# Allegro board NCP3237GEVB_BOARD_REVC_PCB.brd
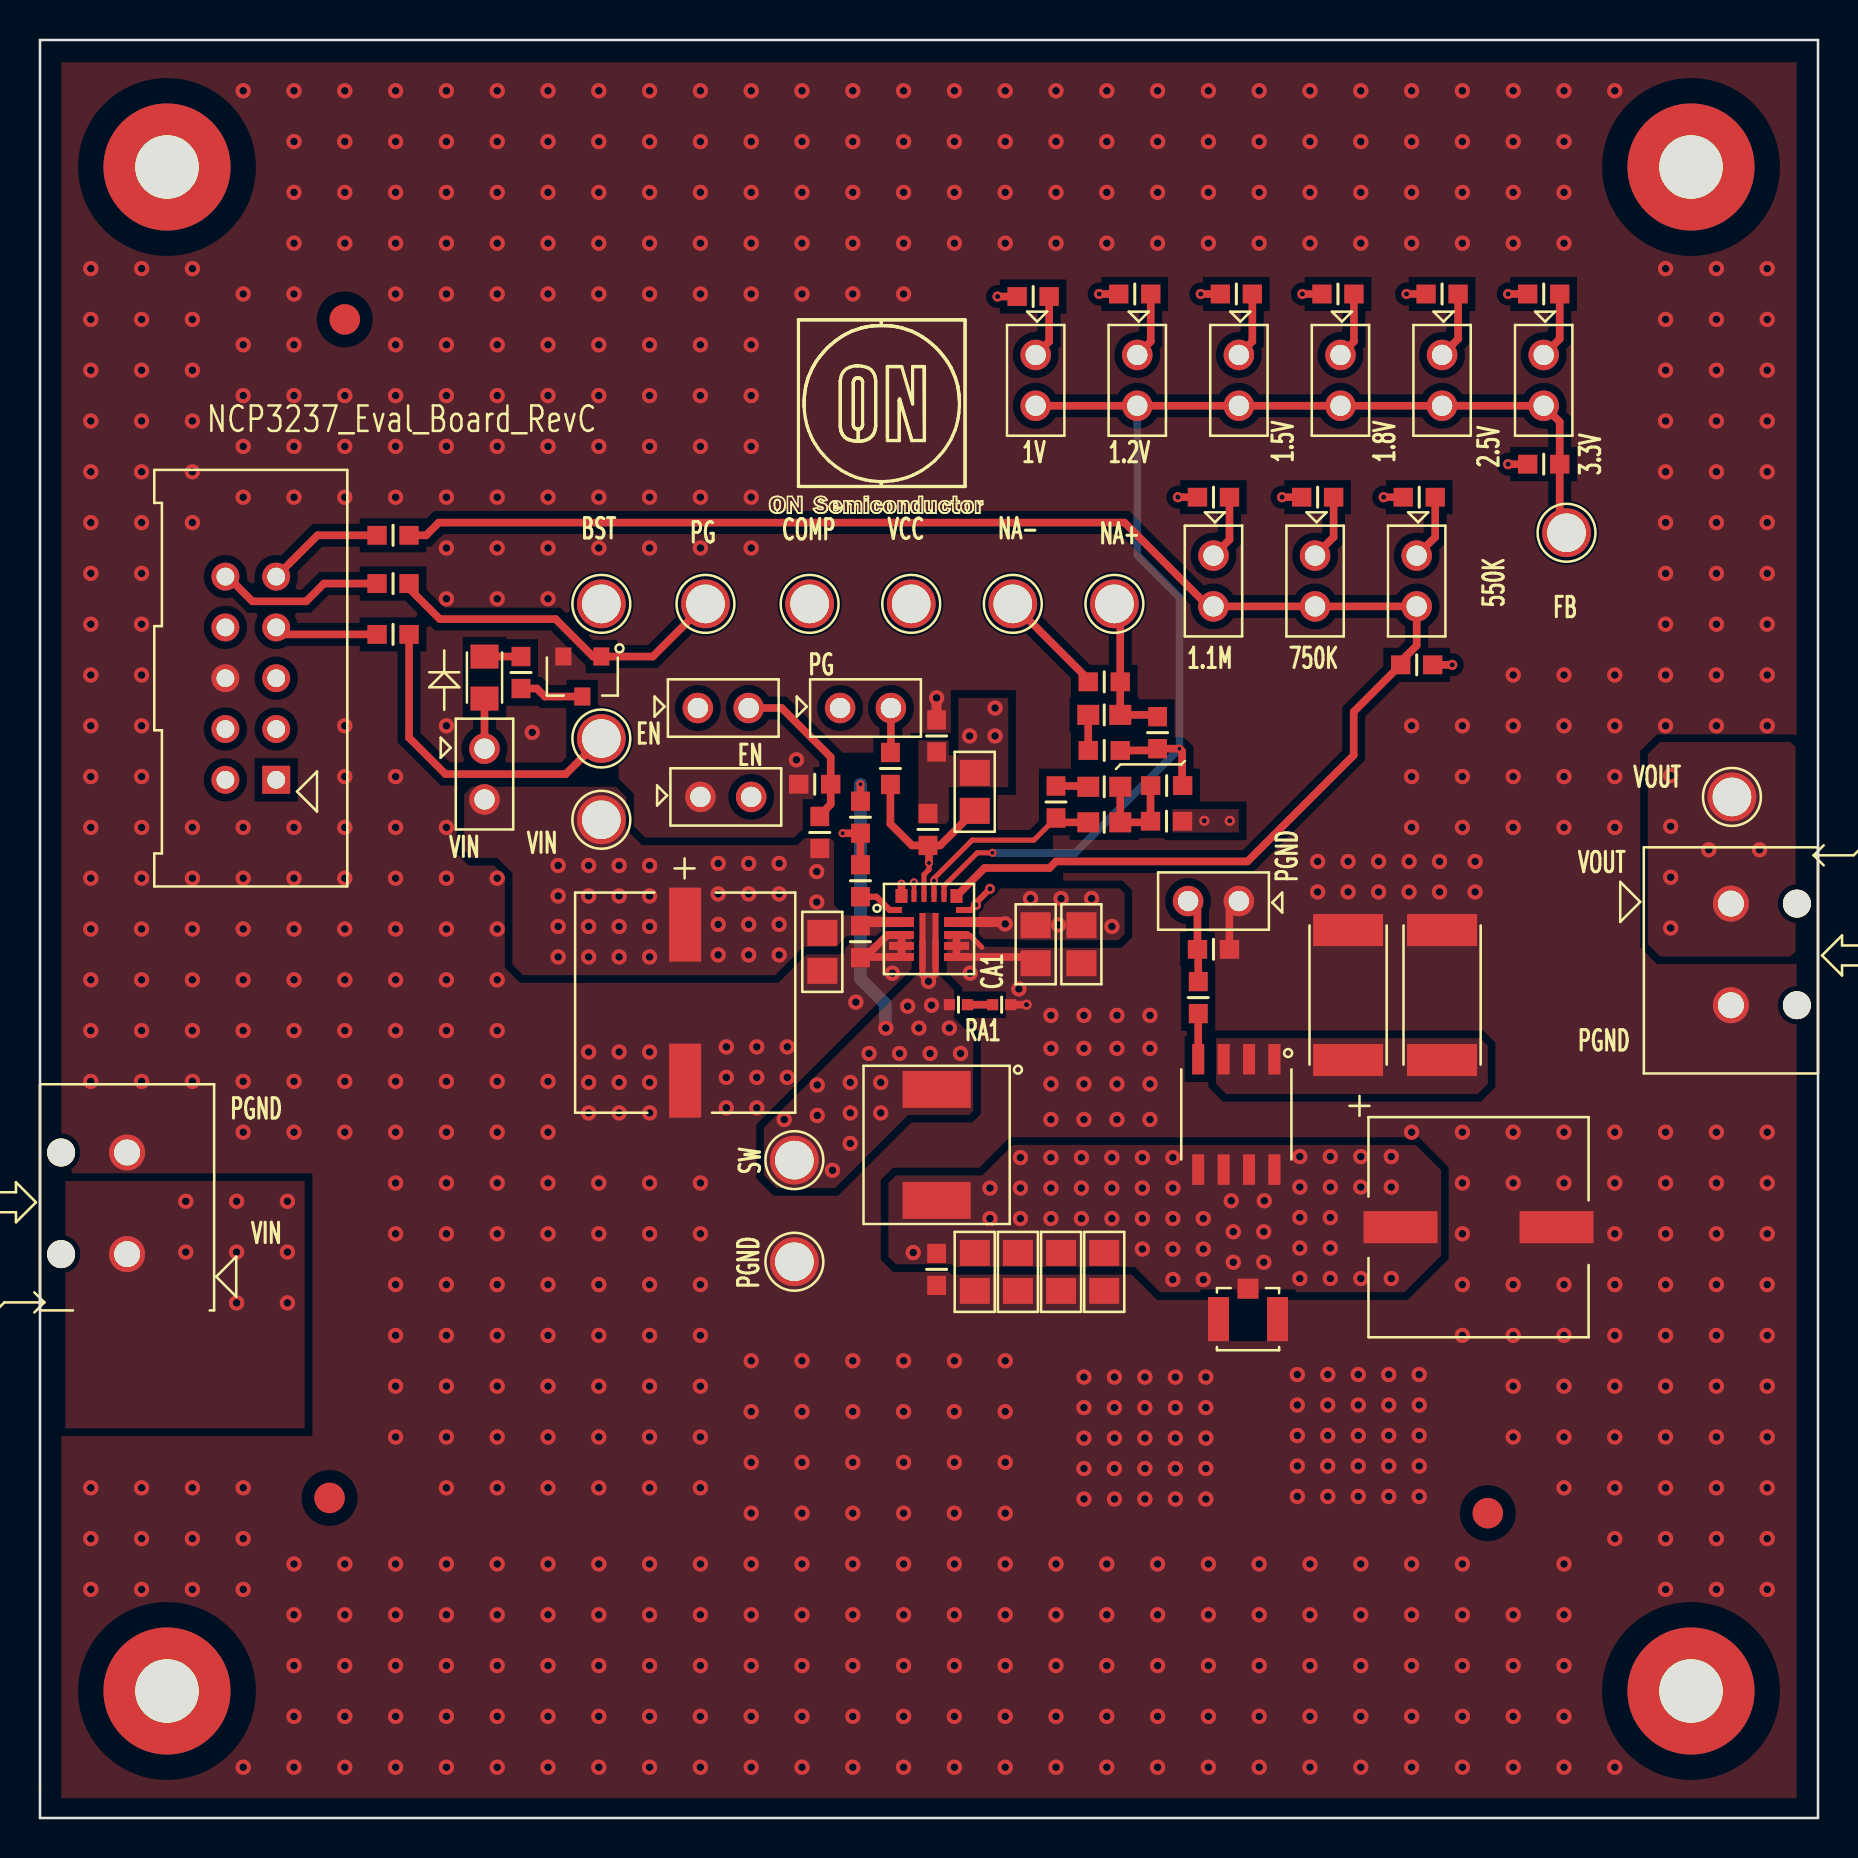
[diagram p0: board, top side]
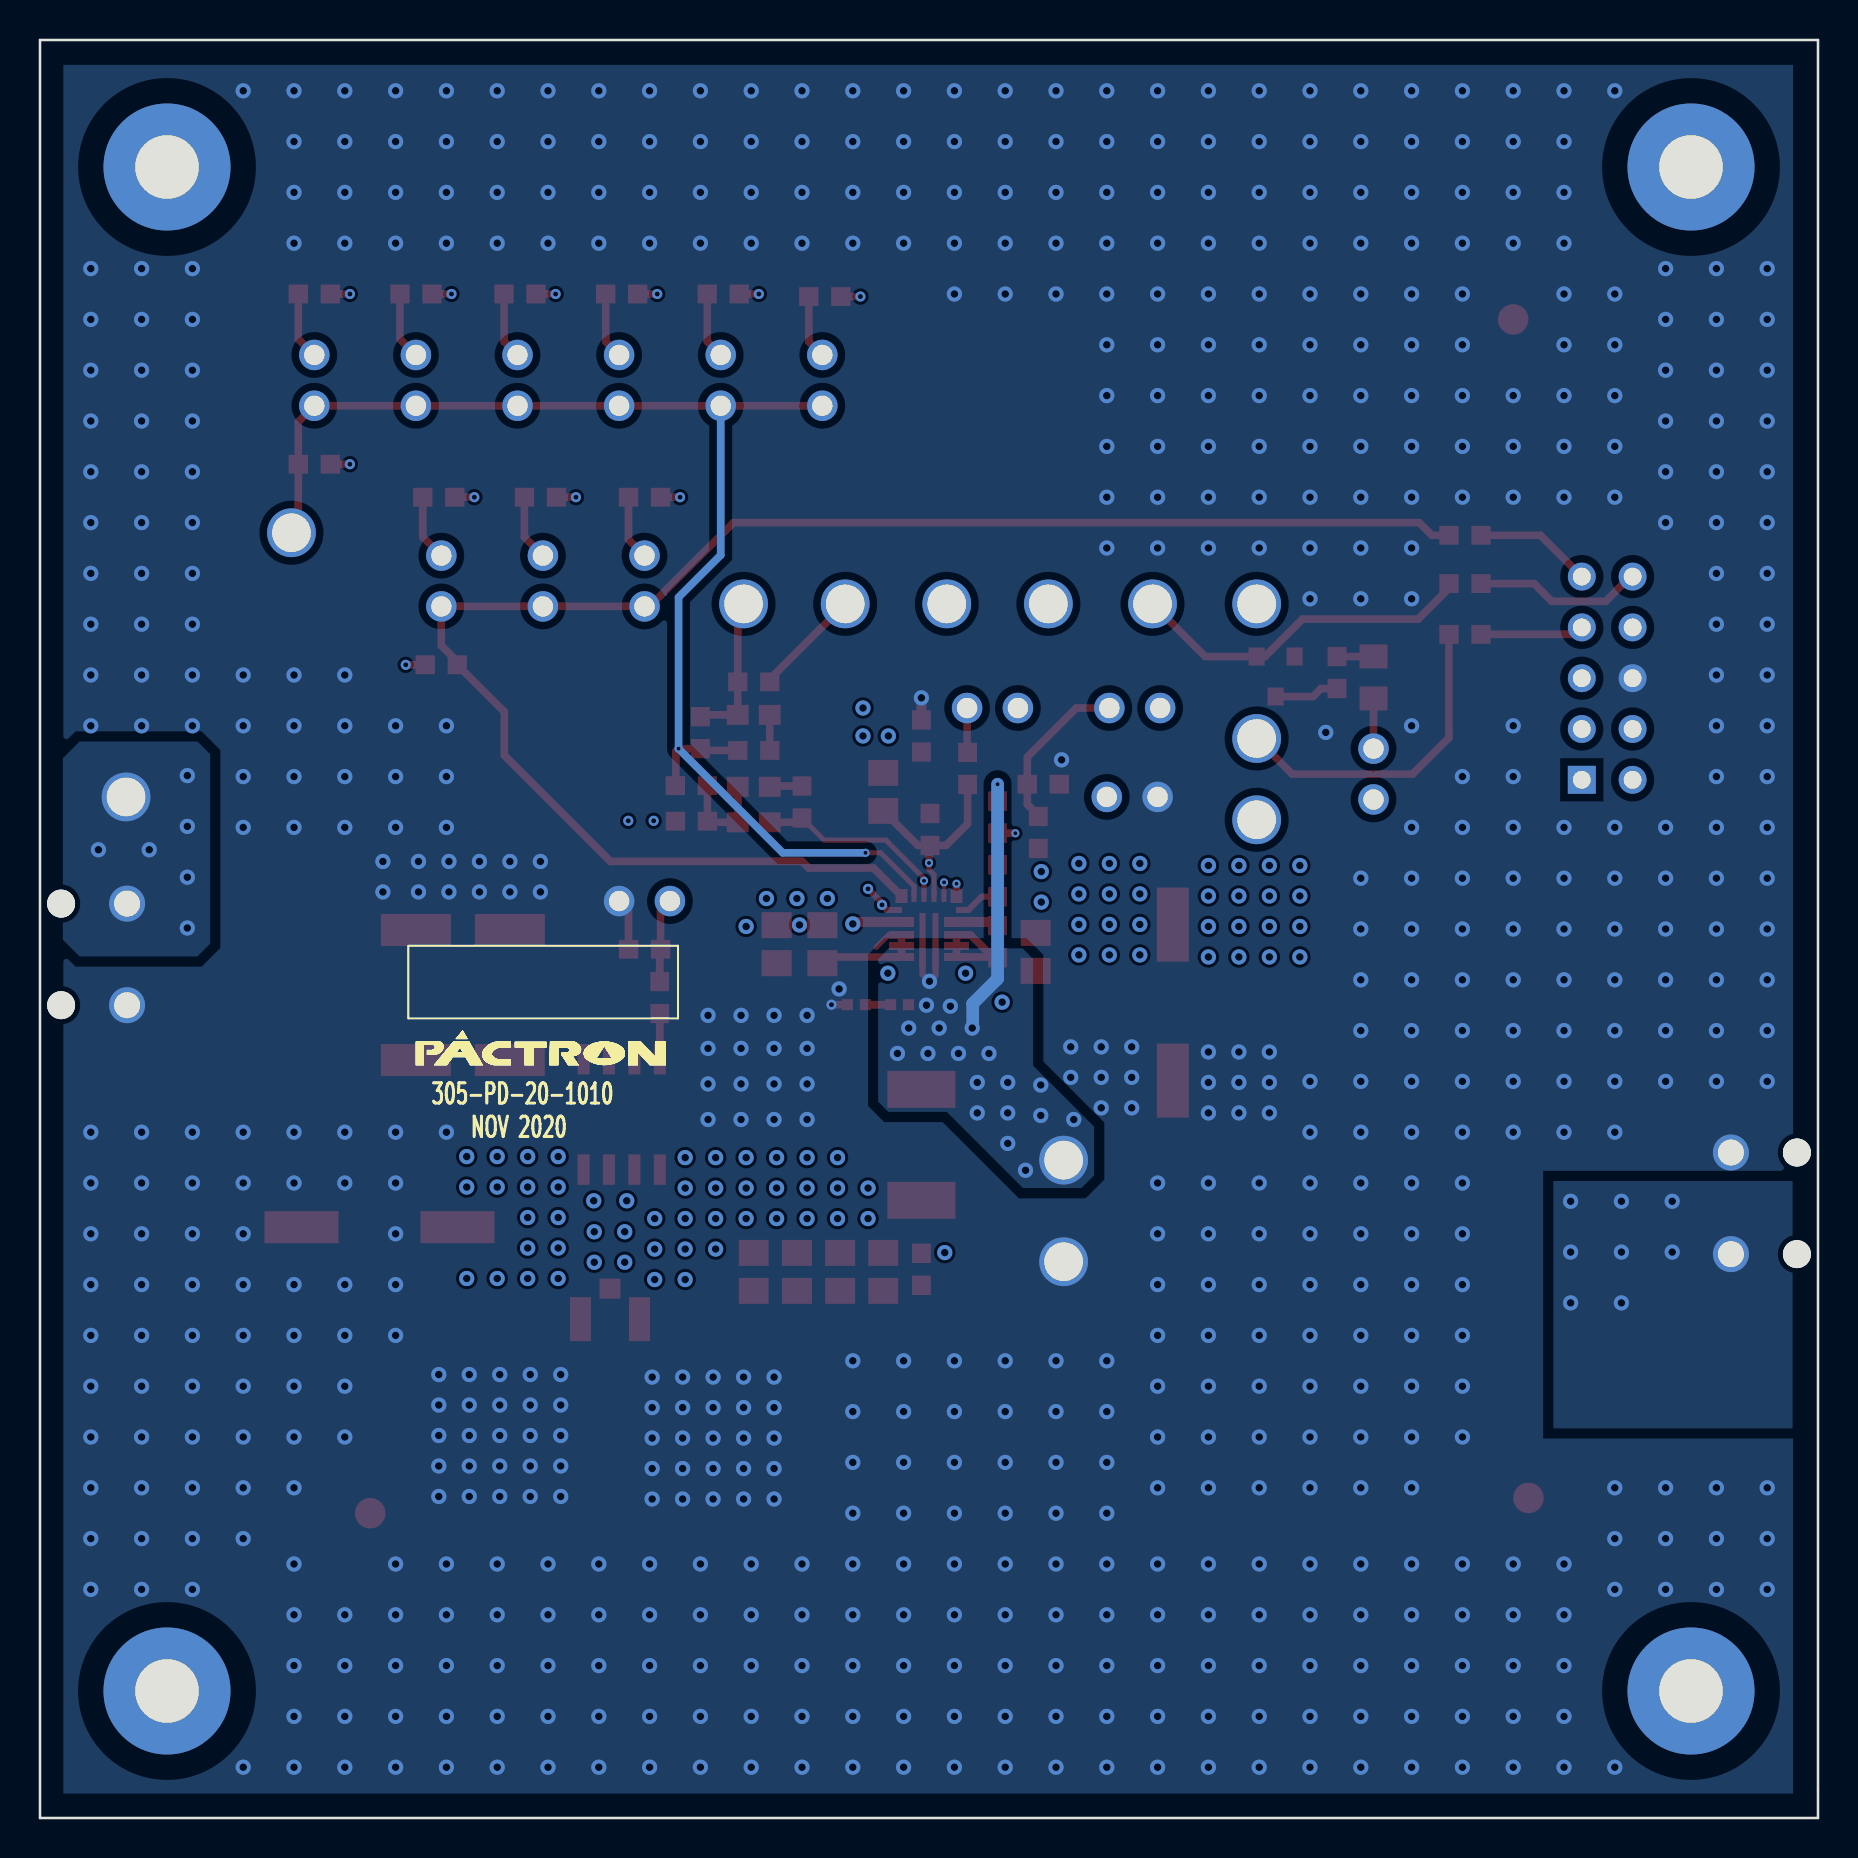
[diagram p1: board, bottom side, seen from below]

Outline 88.9 x 88.9 mm; copper layers: TOP, 02_GND, 03_PWR, BOTTOM. Coordinates in mm from the lower left corner of the outline.
Outline path: 0,88.9 88.9,88.9 88.9,0 0,0 0,88.9

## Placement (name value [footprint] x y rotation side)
C1  22uF  [C0805]  52.07 43.69 270 top
C2  0.1uF  [SMC0603]  41.02 43.81 270 top
C3  0.1uF  [SMC0603]  44.4 49.43 90 top
C4  100uF  [MU_10]  32.26 40.77 270 top
C5  22uF  [C0805]  39.12 43.31 270 top
C6  22uF  [C0805]  49.78 43.69 270 top
C7  0.1uF  [SMC0603]  41.02 50.04 90 top
C8  47uF  [C0805]  46.74 27.3 270 top
C9  47uF  [C0805]  48.9 27.3 270 top
C10  47uF  [C0805]  51.05 27.3 270 top
C11  47uF  [C0805]  53.21 27.3 270 top
C12  0.1uF  [SMC0603]  44.83 27.43 270 top
C13  DNP  [MU_10]  71.93 29.54 0 top
C15  10uF  [C0805]  46.74 51.31 90 top
C17  68pF  [CSMI_0603]  53.21 49.78 180 top
C18  680pF  [CSMI_0603]  53.21 55.16 180 top
C19  1nF  [CSMI_0603]  53.21 51.56 180 top
CA1  DNP  [SMC0402]  48.08 40.67 0 top
D1  GRN  [D0805]  22.23 57.02 270 top
J1  2PIN 1ROW  [JTHI_HDR1R2PS]  58.67 45.85 180 top
J2  2PIN 1ROW  [JTHI_HDR1R2PS]  34.29 51.05 0 top
J3  2PIN 1ROW  [JTHI_HDR1R2PS]  22.23 52.2 270 top
J5  2PIN 1ROW  [JTHI_HDR1R2PS]  49.78 71.88 270 top
J6  2PIN 1ROW  [JTHI_HDR1R2PS]  54.86 71.88 270 top
J7  2PIN 1ROW  [JTHI_HDR1R2PS]  59.94 71.88 270 top
J8  2PIN 1ROW  [JTHI_HDR1R2PS]  58.67 61.85 270 top
J9  2PIN 1ROW  [JTHI_HDR1R2PS]  65.02 71.88 270 top
J10  2PIN 1ROW  [JTHI_HDR1R2PS]  63.75 61.85 270 top
J11  2PIN 1ROW  [JTHI_HDR1R2PS]  70.1 71.88 270 top
J12  2PIN 1ROW  [JTHI_HDR1R2PS]  68.83 61.85 270 top
J13  2PIN 1ROW  [JTHI_HDR1R2PS]  75.18 71.88 270 top
J14  HEADER 5X2_5103308-1  [5103308-1]  10.54 56.99 90 top
J15  2PIN 1ROW  [JTHI_HDR1R2PS]  34.16 55.5 0 top
J16  2PIN 1ROW  [JTHI_HDR1R2PS]  41.27 55.5 0 top
J17  U.FL-R-SMT(10)  [U_FL-R-SMT_10]  60.4 24.94 180 top
L1  1uH  [7_10X6_50X3_00MM]  44.83 33.66 270 top
NOREF  -  []  88.9 88.9 0 top
NOREF#2  -  [unnamed#2]  82.55 6.35 0 top
NOREF#3  -  []  0 0 0 top
NOREF#4  -  [unnamed#2]  82.55 82.55 0 top
NOREF#5  -  []  0 88.9 0 top
NOREF#6  -  [unnamed#2]  15.24 74.93 0 top
NOREF#7  -  []  0 88.9 0 top
NOREF#8  -  [unnamed#2]  6.35 6.35 0 top
NOREF#9  -  [unnamed#2]  72.39 15.24 0 top
NOREF#10  -  []  6.35 82.55 0 top
NOREF#11  -  []  6.35 82.55 0 top
NOREF#12  -  [unnamed#2]  14.48 16 0 top
NOREF#13  -  [unnamed#2]  6.35 82.55 0 top
Q1  NTMS4801  [SO8_PTDSON8_SO8FL_COMBO_8MIL]  59.82 35.18 270 top
Q2  2N7002LT1  [QSMI_SOT23]  27.12 57.07 270 top
R1  DNP  [RSMI_2512]  70.1 41.15 270 top
R2  DNP  [RSMI_2512]  65.41 41.15 270 top
R3  2.0  [SMR0603]  57.91 41.02 90 top
R4  10.0K  [SMR0603]  58.67 43.43 180 top
R5  0.0  [SMR0603]  41.02 46.86 270 top
R6  90.0K  [SMR0603]  38.99 49.28 90 top
R7  30.1K  [SMR0603]  38.73 51.69 180 top
R8  0.0  [SMR0603]  44.83 54.1 270 top
R9  100K  [SMR0603]  42.52 52.48 90 top
R10  10.0  [SMR0603]  53.21 56.81 0 top
R11  150  [SMR0603]  53.21 53.38 0 top
R12  13.7K  [SMR0603]  50.8 50.8 90 top
R13  20K  [SMR0603]  55.88 54.27 270 top
R14  30K  [SMR0603]  49.66 76.07 180 top
R15  20K  [SMR0603]  54.74 76.2 180 top
R16  13.3K  [SMR0603]  59.82 76.2 180 top
R17  511  [SMR0603]  24.05 57.27 270 top
R18  20K  [SMR0603]  58.67 66.04 180 top
R19  10.0K  [SMR0603]  64.9 76.2 180 top
R20  29.4K  [SMR0603]  63.88 66.04 180 top
R21  6.32K  [SMR0603]  70.1 76.2 180 top
R22  40.2K  [SMR0603]  68.96 66.04 180 top
R23  4.42K  [SMR0603]  75.18 76.2 180 top
R24  DNP  [SMR0603]  68.83 57.66 0 top
R25  DNP  [SMR0603]  75.18 67.69 180 top
R26  DNP  [SMR0603]  56.33 49.84 0 top
R27  0  [SMR0603]  56.33 51.62 0 top
R28  0  [SMR0603]  17.65 61.72 0 top
R29  0  [SMR0603]  17.65 64.14 0 top
R30  0  [SMR0603]  17.65 59.18 0 top
RA1  DNP  [SMR0402]  45.92 40.67 0 top
T1  2PIN/TERM BLK  [TERM_BL_2PS]  4.35 30.73 270 top
T2  2PIN/TERM BLK  [TERM_BL_2PS]  84.55 43.18 90 top
TP1  TP  [TPTHI_100R76]  28.07 49.91 0 top
TP2  TP  [TPTHI_100R76]  37.72 32.89 0 top
TP3  TP  [TPTHI_100R76]  28.07 53.98 0 top
TP4  TP  [TPTHI_100R76]  37.72 27.81 0 top
TP5  TP  [TPTHI_100R76]  84.6 51.05 0 top
TP6  TP  [TPTHI_100R76]  38.48 60.71 0 top
TP7  TP  [TPTHI_100R76]  43.56 60.71 0 top
TP8  TP  [TPTHI_100R76]  48.64 60.71 0 top
TP9  TP  [TPTHI_100R76]  53.72 60.71 0 top
TP10  TP  [TPTHI_100R76]  76.33 64.26 0 top
TP11  TP  [TPTHI_100R76]  28.07 60.71 0 top
TP12  TP  [TPTHI_100R76]  33.27 60.71 0 top
U1  NCP3237  [NCP3239]  44.45 44.45 0 top

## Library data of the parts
C1 C3 C5-C12 C15 C17-C19 CA1 = C_2
C2 = C_2: signal model: DEFAULT_CAPACITOR_1pF_1_2
C4 C13 = C_POLARIZED
D1 = LED_0
J1 J3 J5-J13 J15 J16 = J_02PIN_3
J2 = CON2_4
J14 = HEADER 5X2
J17 = BNC
L1 = L
Q1 = Q_NTMS4801NR2G
Q2 = Q_0
R1 R2 = R_0
R3 R5 R8 = R_1
R4 R6 R7 R9 R12-R30 RA1 = R_2
R10 R11 = R
T1 T2 = CON2_3
TP1-TP12 = TP_ROUND
U1 = NCP3239

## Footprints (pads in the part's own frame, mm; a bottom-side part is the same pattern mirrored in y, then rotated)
7_10X6_50X3_00MM
  rect 1.85x3.4 smd: 1(-2.775,0) 2(2.775,0)
5103308-1
  rect 1.397x1.397 hole 0.889: 1(-5.08,-1.27)
  round 1.397 hole 0.889: 2(-5.08,1.27) 3(-2.54,-1.27) 4(-2.54,1.27) 5(0,-1.27) 6(0,1.27) 7(2.54,-1.27) 8(2.54,1.27) 9(5.08,-1.27) 10(5.08,1.27)
C0805
  rect 1.3x1.5 smd: 1(-0.95,0) 2(0.95,0)
CSMI_0603
  rect 1.1x1 smd: 1(-0.8,0) 2(0.8,0)
D0805
  rect 1.2x1.4 smd: 1(1.05,0) 2(-1.05,0)
JTHI_HDR1R2PS
  round 1.524 hole 1.016: 1(-1.27,0) 2(1.27,0)
MU_10
  rect 3.7x1.6 smd: 1(-3.9,0) 2(3.9,0)
NCP3239
  rect 0.6x0.3 smd: 1(-1.65,0.95) 12(1.65,0.95)
  rect 1.25x0.5 smd: 2(-1.375,0.35) 11(1.375,0.35)
  rect 1.25x0.4 smd: 3(-1.375,-0.3) 4(-1.375,-0.85) 5(-1.375,-1.4) 8(1.375,-1.4) 9(1.375,-0.85) 10(1.375,-0.3)
  rect 0.3x2.8 smd: 6(-0.325,-0.6) 7(0.325,-0.6)
  rect 0.6x0.7 smd: 13(1.375,1.65) 18(-1.375,1.65)
  rect 0.25x0.6 smd: 14(0.75,1.65) 15(0.25,1.65) 16(-0.25,1.65) 17(-0.75,1.65)
QSMI_SOT23
  rect 0.9x0.8 smd: 1(-1,0.95) 2(-1,-0.95) 3(1,0)
RSMI_2512
  rect 1.6x3.5 smd: 1(-3.25,0) 2(3.25,0)
SMC0402
  rect 0.559x0.559 smd: 1(-0.45,0) 2(0.45,0)
SMC0603
  rect 0.965x0.94 smd: 1(-0.8,0) 2(0.8,0)
SMR0402
  rect 0.559x0.559 smd: 1(-0.45,0) 2(0.45,0)
SMR0603
  rect 0.965x0.94 smd: 1(-0.8,0) 2(0.8,0)
SO8_PTDSON8_SO8FL_COMBO_8MIL
  rect 1.52x0.6 smd: 1(-2.76,1.905) 2(-2.76,0.635) 3(-2.76,-0.635) 4(-2.76,-1.905) 5(2.76,-1.905) 6(2.76,-0.635) 7(2.76,0.635) 8(2.76,1.905)
TERM_BL_2PS
  round 1.4 hole 1.4 unplated: (-2.54,-3.3) (2.54,-3.3)
  round 1.8 hole 1.3: 1(2.54,0) 2(-2.54,0)
TPTHI_100R76
  round 2.438 hole 1.93: 1(0,0)
U_FL-R-SMT_10
  rect 1.05x1 smd: 1(0,-1.525)
  rect 1.05x2.2 smd: 2(1.475,0) 3(-1.475,0)
unnamed#2
  round 6.35 hole 3.175 unplated: (0,0)

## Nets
GND_SIGNAL_B: C3.2 C15.2 R8.2 R14.2 R15.2 R16.2 R18.2 R19.2 R20.2 R21.2 R22.2 R23.2 R24.2 R25.2 R26.2 U1.12(AGND)
PGND: C1.2 C2.2 C4.2(NEG) C5.2 C6.2 C8.2 C9.2 C10.2 C11.2 C12.2 C13.2(NEG) CA1.2 J1.1 J2.1 J14.6 J17.2(SHIELD1) J17.3(SHIELD2) Q2.2(SOURCE) R1.1 R2.1 R4.1 R7.2 R8.1 T1.2 T2.2 TP4.1 U1.3(PGND1) U1.4(PGND2) U1.5(PGND3) U1.8(PGND4) U1.9(PGND5) U1.10(PGND6)
VIN: C1.1 C2.1 C4.1(POS) C5.1 C6.1 J3.2 R6.1 T1.1 TP1.1 U1.2(VIN1) U1.11(VIN2)
BST: R5.2 U1.1(BST)
COMP: C17.2 R12.1 TP6.1 U1.15(COMP)
EN: J2.2 J15.1 R30.2 TP3.1 U1.17(EN)
FB: J5.2 J6.2 J7.2 J9.2 J11.2 J13.2 R11.2 R13.2 R25.1 R27.2 TP10.1 U1.14(FB)
FSET: J8.2 J10.2 J12.2 R24.1 R29.2 U1.13(FSET)
NA+: C18.1 R10.2 R13.1 TP9.1
PG: J16.1 Q2.1(GATE) R28.2 TP12.1 U1.18(PGOOD)
SW: C7.2 L1.1 RA1.1 TP2.1 U1.6(SW1) U1.7(SW2)
VOUT: C8.1 C9.1 C10.1 C11.1 C12.1 C13.1(POS) J17.1(CENTER) L1.2 Q1.5(DRAIN5) Q1.6(DRAIN6) Q1.7(DRAIN7) Q1.8(DRAIN8) R10.1 T2.1 TP5.1 TP8.1
N16789551: C19.2 R12.2
N16789670: J5.1 R14.1
N16789692: J6.1 R15.1
N16789714: J7.1 R16.1
N16789742: J9.1 R19.1
N16789764: J11.1 R21.1
N16789776: J13.1 R23.1
N16792987: Q1.1(SOURCE1) Q1.2(SOURCE2) Q1.3(SOURCE3) R1.2 R2.2
N16793020: J1.2 R3.2 R4.2
N16793026: Q1.4(GATE) R3.1
N16793275: Q2.3(DRAIN) R17.2
N16793363: C3.1 C15.1 R9.1 TP7.1 U1.16(VCC)
N16793705: J8.1 R18.1
N16793731: J10.1 R20.1
N16793749: J12.1 R22.1
N16797798: C7.1 R5.1 TP11.1
N16798023: CA1.1 RA1.2
N16816279: C17.1 C19.1 R26.1 R27.1
N16820769: D1.2(CATHODE) R17.1
N16820774: D1.1(ANODE) J3.1
N16826315: J14.10 R28.1
N16826318: J14.9 R29.1
N16826340: J14.7 R30.1
N16827137: J15.2 R6.2 R7.1
N16827915: J16.2 R9.2
N167900601: C18.2 R11.1

Pads without a net: J14 1 2 3 4 5 8

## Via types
v1: diameter 0.406, hole 0.203, TOP to BOTTOM, 8 vias
v2: diameter 0.508, hole 0.254, TOP to BOTTOM, 16 vias
v3: diameter 0.762, hole 0.381, TOP to BOTTOM, 809 vias

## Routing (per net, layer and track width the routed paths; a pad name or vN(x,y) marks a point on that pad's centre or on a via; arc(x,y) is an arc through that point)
GND_SIGNAL_B: length 12.7
  TOP w0.305: U1.12 46.54,45.4 v2(46.8,45.66) 46.8,45.76 v2(47.5,46.46)
  TOP w0.381: R16.2 v2(58.04,76.2) ; R20.2 v2(62.1,66.04) ; R22.2 v2(67.18,66.04) ; R14.2 v2(47.88,76.07) ; R18.2 v2(56.9,66.04) ; R15.2 v2(52.96,76.2) ; R24.2 v2(70.61,57.66) ; R19.2 v2(63.12,76.2) ; R25.2 v2(73.41,67.69) ; R21.2 v2(68.33,76.2) ; R23.2 v2(73.41,76.2)
  vias: v2(58.22,49.86) v2(59.49,49.86) v3(46.48,54.1) v3(47.75,55.5) v3(47.75,54.1)
PGND: length 16.9
  TOP w0.254: 47.09,43.54 46.48,44.15 U1.10
  TOP w0.381: J1.1 59.47,45.38 R4.1 ; U1.10 U1.9 U1.8 49.47,43.05 C6.2 ; CA1.2 v2(49.33,40.67) ; C2.2 41.24,43.01 42.37,44.15 U1.3 U1.4 U1.5 41.06,43.05 C2.2
  TOP w0.508: R8.1 v3(44.83,56.01)
  vias: v3(2.54,77.47) v3(2.54,74.93) v3(2.54,72.39) v3(2.54,69.85) v3(2.54,67.31) v3(2.54,64.77) v3(2.54,62.23) v3(2.54,59.69) v3(2.54,57.15) v3(2.54,54.61) v3(2.54,52.07) v3(2.54,49.53) v3(2.54,46.99) v3(2.54,44.45) v3(2.54,41.91) v3(2.54,39.37) v3(2.54,36.83) v3(2.54,16.51) v3(2.54,13.97) v3(2.54,11.43) v3(5.08,77.47) v3(5.08,74.93) v3(5.08,72.39) v3(5.08,69.85) v3(5.08,67.31) v3(5.08,64.77) v3(5.08,62.23) v3(5.08,59.69) v3(5.08,57.15) v3(5.08,54.61) v3(5.08,52.07) v3(5.08,49.53) v3(5.08,46.99) v3(5.08,44.45) v3(5.08,41.91) v3(5.08,39.37) v3(5.08,36.83) v3(5.08,16.51) v3(5.08,13.97) v3(5.08,11.43) v3(7.62,77.47) v3(7.62,74.93) v3(7.62,72.39) v3(7.62,69.85) v3(7.62,67.31) v3(7.62,64.77) v3(7.62,49.53) v3(7.62,46.99) v3(7.62,44.45) v3(7.62,41.91) v3(7.62,39.37) v3(7.62,36.83) v3(7.62,16.51) v3(7.62,13.97) v3(7.62,11.43) v3(10.16,86.36) v3(10.16,76.2) v3(10.16,73.66) v3(10.16,71.12) v3(10.16,68.58) v3(10.16,66.04) v3(10.16,49.53) v3(10.16,46.99) v3(10.16,44.45) v3(10.16,41.91) v3(10.16,39.37) v3(10.16,36.83) v3(10.16,34.29) v3(10.16,16.51) v3(10.16,13.97) v3(10.16,11.43) v3(10.16,2.54) v3(12.7,86.36) v3(12.7,83.82) v3(12.7,81.28) v3(12.7,78.74) v3(12.7,76.2) v3(12.7,73.66) v3(12.7,71.12) v3(12.7,68.58) v3(12.7,66.04) v3(12.7,49.53) v3(12.7,46.99) v3(12.7,44.45) v3(12.7,41.91) v3(12.7,39.37) v3(12.7,36.83) v3(12.7,34.29) v3(12.7,12.7) v3(12.7,10.16) v3(12.7,7.62) v3(12.7,5.08) v3(12.7,2.54) v3(15.24,86.36) v3(15.24,83.82) v3(15.24,81.28) v3(15.24,78.74) v3(15.24,71.12) v3(15.24,68.58) v3(15.24,66.04) v3(15.24,54.61) v3(15.24,52.07) v3(15.24,49.53) v3(15.24,46.99) v3(15.24,44.45) v3(15.24,41.91) v3(15.24,39.37) v3(15.24,36.83) v3(15.24,34.29) v3(15.24,12.7) v3(15.24,10.16) v3(15.24,7.62) v3(15.24,5.08) v3(15.24,2.54) v3(17.78,86.36) v3(17.78,83.82) v3(17.78,81.28) v3(17.78,78.74) v3(17.78,76.2) v3(17.78,73.66) v3(17.78,71.12) v3(17.78,68.58) v3(17.78,66.04) v3(17.78,52.07) v3(17.78,49.53) v3(17.78,46.99) v3(17.78,44.45) v3(17.78,41.91) v3(17.78,39.37) v3(17.78,36.83) v3(17.78,34.29) v3(17.78,31.75) v3(17.78,29.21) v3(17.78,26.67) v3(17.78,24.13) v3(17.78,21.59) v3(17.78,19.05) v3(17.78,12.7) v3(17.78,10.16) v3(17.78,7.62) v3(17.78,5.08) v3(17.78,2.54) v3(20.32,86.36) v3(20.32,83.82) v3(20.32,81.28) v3(20.32,78.74) v3(20.32,76.2) v3(20.32,73.66) v3(20.32,71.12) v3(20.32,68.58) v3(20.32,66.04) v3(20.32,63.5) v3(20.32,60.96) v3(20.32,54.61) v3(20.32,49.53) v3(20.32,46.99) v3(20.32,44.45) v3(20.32,41.91) v3(20.32,39.37) v3(20.32,36.83) v3(20.32,34.29) v3(20.32,31.75) v3(20.32,29.21) v3(20.32,26.67) v3(20.32,24.13) v3(20.32,21.59) v3(20.32,19.05) v3(20.32,16.51) v3(20.32,12.7) v3(20.32,10.16) v3(20.32,7.62) v3(20.32,5.08) v3(20.32,2.54) v3(22.86,86.36) v3(22.86,83.82) v3(22.86,81.28) v3(22.86,78.74) v3(22.86,76.2) v3(22.86,73.66) v3(22.86,71.12) v3(22.86,68.58) v3(22.86,66.04) v3(22.86,63.5) v3(22.86,60.96) v3(22.86,46.99) v3(22.86,44.45) v3(22.86,41.91) v3(22.86,39.37) v3(22.86,36.83) v3(22.86,34.29) v3(22.86,31.75) v3(22.86,29.21) v3(22.86,26.67) v3(22.86,24.13) v3(22.86,21.59) v3(22.86,19.05) v3(22.86,16.51) v3(22.86,12.7) v3(22.86,10.16) v3(22.86,7.62) v3(22.86,5.08) v3(22.86,2.54) v3(24.61,54.28) v3(25.4,86.36) v3(25.4,83.82) v3(25.4,81.28) v3(25.4,78.74) v3(25.4,76.2) v3(25.4,73.66) v3(25.4,71.12) v3(25.4,68.58) v3(25.4,66.04) v3(25.4,63.5) v3(25.4,60.96) v3(25.4,36.83) v3(25.4,34.29) v3(25.4,31.75) v3(25.4,29.21) v3(25.4,26.67) v3(25.4,24.13) v3(25.4,21.59) v3(25.4,19.05) v3(25.4,16.51) v3(25.4,12.7) v3(25.4,10.16) v3(25.4,7.62) v3(25.4,5.08) v3(25.4,2.54) v3(27.43,38.3) v3(27.43,36.78) v3(27.43,35.25) v3(27.94,86.36) v3(27.94,83.82) v3(27.94,81.28) v3(27.94,78.74) v3(27.94,76.2) v3(27.94,73.66) v3(27.94,71.12) v3(27.94,68.58) v3(27.94,66.04) v3(27.94,63.5) v3(27.94,31.75) v3(27.94,29.21) v3(27.94,26.67) v3(27.94,24.13) v3(27.94,21.59) v3(27.94,19.05) v3(27.94,16.51) v3(27.94,12.7) v3(27.94,10.16) v3(27.94,7.62) v3(27.94,5.08) v3(27.94,2.54) v3(28.96,38.3) v3(28.96,36.78) v3(28.96,35.25) v3(30.48,86.36) v3(30.48,83.82) v3(30.48,81.28) v3(30.48,78.74) v3(30.48,76.2) v3(30.48,73.66) v3(30.48,71.12) v3(30.48,68.58) v3(30.48,66.04) v3(30.48,63.5) v3(30.48,38.3) v3(30.48,36.78) v3(30.48,35.25) v3(30.48,31.75) v3(30.48,29.21) v3(30.48,26.67) v3(30.48,24.13) v3(30.48,21.59) v3(30.48,19.05) v3(30.48,16.51) v3(30.48,12.7) v3(30.48,10.16) v3(30.48,7.62) v3(30.48,5.08) v3(30.48,2.54) v3(33.02,86.36) v3(33.02,83.82) v3(33.02,81.28) v3(33.02,78.74) v3(33.02,76.2) v3(33.02,73.66) v3(33.02,71.12) v3(33.02,68.58) v3(33.02,66.04) v3(33.02,63.5) v3(33.02,31.75) v3(33.02,29.21) v3(33.02,26.67) v3(33.02,24.13) v3(33.02,21.59) v3(33.02,19.05) v3(33.02,16.51) v3(33.02,12.7) v3(33.02,10.16) v3(33.02,7.62) v3(33.02,5.08) v3(33.02,2.54) v3(34.32,38.56) v3(34.32,37.03) v3(34.32,35.51) v3(35.56,86.36) v3(35.56,83.82) v3(35.56,81.28) v3(35.56,78.74) v3(35.56,76.2) v3(35.56,73.66) v3(35.56,71.12) v3(35.56,68.58) v3(35.56,66.04) v3(35.56,63.5) v3(35.56,22.86) v3(35.56,20.32) v3(35.56,17.78) v3(35.56,15.24) v3(35.56,12.7) v3(35.56,10.16) v3(35.56,7.62) v3(35.56,5.08) v3(35.56,2.54) v3(35.84,38.56) v3(35.84,37.03) v3(35.84,35.51) v3(37.36,38.56) v3(37.36,37.03) v3(37.82,52.91) v3(38.1,86.36) v3(38.1,83.82) v3(38.1,81.28) v3(38.1,78.74) v3(38.1,76.2) v3(38.1,22.86) v3(38.1,20.32) v3(38.1,17.78) v3(38.1,15.24) v3(38.1,12.7) v3(38.1,10.16) v3(38.1,7.62) v3(38.1,5.08) v3(38.1,2.54) v3(40.64,86.36) v3(40.64,83.82) v3(40.64,81.28) v3(40.64,78.74) v3(40.64,76.2) v3(40.64,22.86) v3(40.64,20.32) v3(40.64,17.78) v3(40.64,15.24) v3(40.64,12.7) v3(40.64,10.16) v3(40.64,7.62) v3(40.64,5.08) v3(40.64,2.54) v3(40.79,40.79) v3(42.62,42.24) v3(43.18,86.36) v3(43.18,83.82) v3(43.18,81.28) v3(43.18,78.74) v3(43.18,76.2) v3(43.18,22.86) v3(43.18,20.32) v3(43.18,17.78) v3(43.18,15.24) v3(43.18,12.7) v3(43.18,10.16) v3(43.18,7.62) v3(43.18,5.08) v3(43.18,2.54) v3(45.72,86.36) v3(45.72,83.82) v3(45.72,81.28) v3(45.72,78.74) v3(45.72,22.86) v3(45.72,20.32) v3(45.72,17.78) v3(45.72,15.24) v3(45.72,12.7) v3(45.72,10.16) v3(45.72,7.62) v3(45.72,5.08) v3(45.72,2.54) v3(46.51,42.24) v3(48.26,86.36) v3(48.26,83.82) v3(48.26,81.28) v3(48.26,78.74) v3(48.26,22.86) v3(48.26,20.32) v3(48.26,17.78) v3(48.26,15.24) v3(48.26,12.7) v3(48.26,10.16) v3(48.26,7.62) v3(48.26,5.08) v3(48.26,2.54) v3(48.95,41.45) v3(50.55,40.13) v3(50.55,38.48) v3(50.55,36.7) v3(50.55,34.92) v3(50.8,86.36) v3(50.8,83.82) v3(50.8,81.28) v3(50.8,78.74) v3(50.8,12.7) v3(50.8,10.16) v3(50.8,7.62) v3(50.8,5.08) v3(50.8,2.54) v3(52.2,40.13) v3(52.2,38.48) v3(52.2,36.7) v3(52.2,34.92) v3(52.2,22.05) v3(52.2,20.52) v3(52.2,19) v3(52.2,17.47) v3(52.2,15.95) v3(53.34,86.36) v3(53.34,83.82) v3(53.34,81.28) v3(53.34,78.74) v3(53.34,12.7) v3(53.34,10.16) v3(53.34,7.62) v3(53.34,5.08) v3(53.34,2.54) v3(53.72,22.05) v3(53.72,20.52) v3(53.72,19) v3(53.72,17.47) v3(53.72,15.95) v3(53.85,40.13) v3(53.85,38.48) v3(53.85,36.7) v3(53.85,34.92) v3(55.24,22.05) v3(55.24,20.52) v3(55.24,19) v3(55.24,17.47) v3(55.24,15.95) v3(55.5,40.13) v3(55.5,38.48) v3(55.5,36.7) v3(55.5,34.92) v3(55.88,86.36) v3(55.88,83.82) v3(55.88,81.28) v3(55.88,78.74) v3(55.88,12.7) v3(55.88,10.16) v3(55.88,7.62) v3(55.88,5.08) v3(55.88,2.54) v3(56.77,22.05) v3(56.77,20.52) v3(56.77,19) v3(56.77,17.47) v3(56.77,15.95) v3(58.29,22.05) v3(58.29,20.52) v3(58.29,19) v3(58.29,17.47) v3(58.29,15.95) v3(58.42,86.36) v3(58.42,83.82) v3(58.42,81.28) v3(58.42,78.74) v3(58.42,12.7) v3(58.42,10.16) v3(58.42,7.62) v3(58.42,5.08) v3(58.42,2.54) v3(60.96,86.36) v3(60.96,83.82) v3(60.96,81.28) v3(60.96,78.74) v3(60.96,12.7) v3(60.96,10.16) v3(60.96,7.62) v3(60.96,5.08) v3(60.96,2.54) v3(62.87,22.17) v3(62.87,20.65) v3(62.87,19.12) v3(62.87,17.6) v3(62.87,16.08) v3(63.5,86.36) v3(63.5,83.82) v3(63.5,81.28) v3(63.5,78.74) v3(63.5,12.7) v3(63.5,10.16) v3(63.5,7.62) v3(63.5,5.08) v3(63.5,2.54) v3(63.88,47.83) v3(63.88,46.3) v3(64.39,22.17) v3(64.39,20.65) v3(64.39,19.12) v3(64.39,17.6) v3(64.39,16.08) v3(65.41,47.83) v3(65.41,46.3) v3(65.91,22.17) v3(65.91,20.65) v3(65.91,19.12) v3(65.91,17.6) v3(65.91,16.08) v3(66.04,86.36) v3(66.04,83.82) v3(66.04,81.28) v3(66.04,78.74) v3(66.04,12.7) v3(66.04,10.16) v3(66.04,7.62) v3(66.04,5.08) v3(66.04,2.54) v3(66.93,47.83) v3(66.93,46.3) v3(67.44,22.17) v3(67.44,20.65) v3(67.44,19.12) v3(67.44,17.6) v3(67.44,16.08) v3(68.45,47.83) v3(68.45,46.3) v3(68.58,86.36) v3(68.58,83.82) v3(68.58,81.28) v3(68.58,78.74) v3(68.58,54.61) v3(68.58,52.07) v3(68.58,49.53) v3(68.58,34.29) v3(68.58,12.7) v3(68.58,10.16) v3(68.58,7.62) v3(68.58,5.08) v3(68.58,2.54) v3(68.96,22.17) v3(68.96,20.65) v3(68.96,19.12) v3(68.96,17.6) v3(68.96,16.08) v3(69.98,47.83) v3(69.98,46.3) v3(71.12,86.36) v3(71.12,83.82) v3(71.12,81.28) v3(71.12,78.74) v3(71.12,54.61) v3(71.12,52.07) v3(71.12,49.53) v3(71.12,34.29) v3(71.12,31.75) v3(71.12,29.21) v3(71.12,26.67) v3(71.12,24.13) v3(71.12,12.7) v3(71.12,10.16) v3(71.12,7.62) v3(71.12,5.08) v3(71.12,2.54) v3(71.75,47.83) v3(71.75,46.3) v3(73.66,86.36) v3(73.66,83.82) v3(73.66,81.28) v3(73.66,78.74) v3(73.66,57.15) v3(73.66,54.61) v3(73.66,52.07) v3(73.66,49.53) v3(73.66,34.29) v3(73.66,31.75) v3(73.66,26.67) v3(73.66,24.13) v3(73.66,21.59) v3(73.66,19.05) v3(73.66,10.16) v3(73.66,7.62) v3(73.66,5.08) v3(73.66,2.54) v3(76.2,86.36) v3(76.2,83.82) v3(76.2,81.28) v3(76.2,78.74) v3(76.2,57.15) v3(76.2,54.61) v3(76.2,52.07) v3(76.2,49.53) v3(76.2,34.29) v3(76.2,31.75) v3(76.2,26.67) v3(76.2,24.13) v3(76.2,21.59) v3(76.2,19.05) v3(76.2,16.51) v3(76.2,12.7) v3(76.2,10.16) v3(76.2,7.62) v3(76.2,5.08) v3(76.2,2.54) v3(78.74,86.36) v3(78.74,57.15) v3(78.74,54.61) v3(78.74,52.07) v3(78.74,49.53) v3(78.74,34.29) v3(78.74,31.75) v3(78.74,29.21) v3(78.74,26.67) v3(78.74,24.13) v3(78.74,21.59) v3(78.74,19.05) v3(78.74,16.51) v3(78.74,13.97) v3(78.74,2.54) v3(81.28,77.47) v3(81.28,74.93) v3(81.28,72.39) v3(81.28,69.85) v3(81.28,67.31) v3(81.28,64.77) v3(81.28,62.23) v3(81.28,59.69) v3(81.28,57.15) v3(81.28,54.61) v3(81.28,34.29) v3(81.28,31.75) v3(81.28,29.21) v3(81.28,26.67) v3(81.28,24.13) v3(81.28,21.59) v3(81.28,19.05) v3(81.28,16.51) v3(81.28,13.97) v3(81.28,11.43) v3(83.82,77.47) v3(83.82,74.93) v3(83.82,72.39) v3(83.82,69.85) v3(83.82,67.31) v3(83.82,64.77) v3(83.82,62.23) v3(83.82,59.69) v3(83.82,57.15) v3(83.82,54.61) v3(83.82,34.29) v3(83.82,31.75) v3(83.82,29.21) v3(83.82,26.67) v3(83.82,24.13) v3(83.82,21.59) v3(83.82,19.05) v3(83.82,16.51) v3(83.82,13.97) v3(83.82,11.43) v3(86.36,77.47) v3(86.36,74.93) v3(86.36,72.39) v3(86.36,69.85) v3(86.36,67.31) v3(86.36,64.77) v3(86.36,62.23) v3(86.36,59.69) v3(86.36,57.15) v3(86.36,54.61) v3(86.36,34.29) v3(86.36,31.75) v3(86.36,29.21) v3(86.36,26.67) v3(86.36,24.13) v3(86.36,21.59) v3(86.36,19.05) v3(86.36,16.51) v3(86.36,13.97) v3(86.36,11.43)
VIN: length 4.6
  TOP w0.508: v3(48.26,44.7) 48.16,44.8 U1.11 ; U1.2 41.21,44.8 C2.1
  vias: v3(7.29,30.84) v3(7.29,28.3) v3(9.83,30.84) v3(9.83,28.3) v3(9.83,25.76) v3(12.37,30.84) v3(12.37,28.3) v3(12.37,25.76) v3(25.91,47.62) v3(25.91,46.1) v3(25.91,44.58) v3(25.91,43.05) v3(27.43,47.62) v3(27.43,46.1) v3(27.43,44.58) v3(27.43,43.05) v3(28.96,47.62) v3(28.96,46.1) v3(28.96,44.58) v3(28.96,43.05) v3(30.48,47.62) v3(30.48,46.1) v3(30.48,44.58) v3(30.48,43.05) v3(33.91,47.73) v3(33.91,46.2) v3(33.91,44.68) v3(33.91,43.15) v3(35.43,47.73) v3(35.43,46.2) v3(35.43,44.68) v3(35.43,43.15) v3(36.96,47.73) v3(36.96,46.2) v3(36.96,44.68) v3(36.96,43.15) v3(38.84,47.32) v3(38.84,45.8) v3(49.53,45.97) v3(50.93,44.65) v3(51.05,45.97) v3(52.58,45.97) v3(53.59,44.58)
BST: length 2.1
  TOP w0.305: R5.2 41.82,46.06 42.48,45.4 U1.1
COMP: length 26.5
  TOP w0.254: R12.1 49.7,48.9 46.61,48.9 44.7,46.99 v1(44.7,46.86) U1.15
  TOP w0.381: R12.1 51.02,49.78 C17.2
  02_GND w0.381: TP6.1 41.27,57.91 41.27,54.36 43.18,52.45 43.18,48.15 44.47,46.86 v1(44.7,46.86)
EN: length 38.9
  TOP w0.229: v1(43.7,46.78) 43.7,46.78 U1.17
  TOP w0.381: R30.2 18.45,54.01 20.27,52.2 26.29,52.2 TP3.1
  02_GND w0.381: TP3.1 29.59,55.5 J15.1 32.89,53.72 J2.2 36.07,50.55 36.83,50.55 41.4,45.97 43.43,45.97 43.7,46.24 43.7,46.78 v1(43.7,46.78)
FB: length 70.3
  TOP w0.254: v1(47.62,48.26) 46.86,48.26 45.2,46.6 U1.14
  TOP w0.381: TP10.1 75.98,64.6 R25.1 75.98,69.81 J13.2 J11.2 J9.2 J7.2 J6.2 J5.2 ; R27.2 57.11,51.64 57.11,53.33 v1(56.97,53.47) R13.2 55.79,53.38 R11.2
  BOTTOM w0.381: J6.2 54.86,63.14 56.97,61.04 v1(56.97,53.47) 51.77,48.26 v1(47.62,48.26)
FSET: length 83.9
  TOP w0.381: U1.13 47.22,47.5 50.47,47.5 50.8,47.83 60.38,47.83 65.68,53.14 65.68,55.31 R24.1 68.03,57.82 68.83,58.62 68.83,60.58 58.42,60.58 54.23,64.77 19.94,64.77 19.3,64.14 R29.2
NA+: length 7.6
  TOP w0.381: R13.1 55.79,55.16 C18.1 R10.2 54.01,60.41 TP9.1
PG: length 37.4
  TOP w0.381: TP12.1 30.64,58.07 Q2.1 27.65,58.07 25.78,59.94 19.99,59.94 18.45,61.48 R28.2 ; v1(43.08,46.71) U1.18
  02_GND w0.381: v1(43.08,46.71) 42.6,46.71 42.21,47.09 42.21,52.15 40.01,54.36 J16.1 34.8,60.71 TP12.1
SW: length 17.9
  TOP w0.305: U1.7 44.78,42.18 v3(44.42,41.83) 44.12,42.13 U1.6
  TOP w0.381: C7.2 v1(41.02,51.69)
  BOTTOM w0.635: v3(42.29,39.5) 42.27,39.52 42.27,40.72 41.02,41.96 v1(41.02,51.69)
  vias: v3(37.21,34.92) v3(38.86,36.65) v3(38.86,35.13) v3(39.62,32.38) v3(40.51,36.78) v3(40.51,35.25) v3(40.51,33.73) v3(41.45,38.23) v3(42.04,36.78) v3(42.04,35.25) v3(42.98,38.23) v3(43.38,40.59) v3(43.94,39.5) v3(44.5,38.23) v3(44.58,40.64) v3(45.47,39.5) v3(46.03,38.23)
VOUT: length 5.5
  TOP w0.381: TP8.1 52.41,56.93 R10.1
  vias: v3(43.66,28.27) v3(47.5,31.5) v3(47.5,29.97) v3(49.02,33.02) v3(49.02,31.5) v3(49.02,29.97) v3(50.55,33.02) v3(50.55,31.5) v3(50.55,29.97) v3(52.07,33.02) v3(52.07,31.5) v3(52.07,29.97) v3(53.59,33.02) v3(53.59,31.5) v3(53.59,29.97) v3(55.12,33.02) v3(55.12,31.5) v3(55.12,29.97) v3(55.12,28.45) v3(56.64,33.02) v3(56.64,31.5) v3(56.64,29.97) v3(56.64,28.45) v3(56.64,26.92) v3(58.17,29.97) v3(58.17,28.45) v3(58.17,26.92) v3(59.56,30.86) v3(59.66,29.31) v3(59.66,27.79) v3(61.21,30.86) v3(61.19,29.31) v3(61.19,27.79) v3(62.99,33.07) v3(62.99,31.55) v3(62.99,30.02) v3(62.99,28.5) v3(62.99,26.97) v3(64.52,33.07) v3(64.52,31.55) v3(64.52,30.02) v3(64.52,28.5) v3(64.52,26.97) v3(66.04,33.07) v3(66.04,31.55) v3(66.04,26.97) v3(67.56,33.07) v3(67.56,31.55) v3(67.56,26.97) v3(81.53,52.12) v3(81.53,49.58) v3(81.53,47.04) v3(81.53,44.5) v3(83.44,48.41) v3(85.98,48.41)
N16789551: length 1.6
  TOP w0.381: C19.2 52.37,51.6 R12.2
N16789670: length 3.2
  TOP w0.381: R14.1 50.46,73.83 J5.1
N16789692: length 3.3
  TOP w0.381: J6.1 55.54,73.83 R15.1
N16789714: length 3.3
  TOP w0.381: J7.1 60.62,73.83 R16.1
N16789742: length 3.3
  TOP w0.381: J9.1 65.7,73.83 R19.1
N16789764: length 3.4
  TOP w0.381: J11.1 70.9,73.95 R21.1
N16789776: length 3.4
  TOP w0.381: R23.1 75.98,73.95 J13.1
N16793020: length 4.2
  TOP w0.381: J1.2 57.87,45.38 R4.2 57.91,43.4 R3.2
N16793026: length 2.3
  TOP w0.381: Q1.4 R3.1
N16793275: length 3.2
  TOP w0.381: R17.2 24.85,56.47 25.25,56.07 Q2.3
N16793363: length 23.3
  TOP w0.254: U1.16 44.2,47.17 44.45,47.42 v1(44.45,47.75)
  TOP w0.381: C3.1 43.6,48.63 42.52,49.71 R9.1 ; C3.1 44.45,48.58 v1(44.45,47.75) ; C3.1 45.01,48.63 C15.1
  02_GND w0.381: TP7.1 43.56,57.91 43.99,57.49 43.99,48.22 v1(44.45,47.75)
N16793705: length 3.3
  TOP w0.381: J8.1 59.47,63.92 R18.1
N16793731: length 3.3
  TOP w0.381: R20.1 64.68,64.05 J10.1
N16793749: length 3.3
  TOP w0.381: J12.1 69.76,64.05 R22.1
N16797798: length 21.8
  TOP w0.381: R5.1 C7.1 v1(40.13,49.24)
  02_GND w0.381: v1(40.13,49.24) 39.7,49.67 39.7,52.53 37.85,54.38 37.85,55.78 35.48,58.14 30.63,58.14 TP11.1
N16798023: length 1.3
  TOP w0.381: RA1.2 CA1.1
N16816279: length 5.1
  TOP w0.381: C19.1 C17.1 55.47,49.78 R26.1 55.53,51.61 R27.1
N16820769: length 1.8
  TOP w0.381: D1.2 R17.1
N16820774: length 2.5
  TOP w0.381: D1.1 J3.1
N16826315: length 8.5
  TOP w0.381: R28.1 14.2,61.72 13.31,60.83 10.62,60.83 9.38,62.07 J14.10
N16826318: length 5.9
  TOP w0.381: J14.9 13.88,64.14 R29.1
N16826340: length 5.2
  TOP w0.381: R30.1 12.16,59.18 J14.7
N16827137: length 8.3
  TOP w0.381: R6.2 38.99,50.14 39.54,50.69 R7.1 39.54,53.05 37.08,55.5 J15.2
N16827915: length 2.2
  TOP w0.381: J16.2 42.55,53.3 R9.2
N167900601: length 1.8
  TOP w0.381: C18.2 R11.1

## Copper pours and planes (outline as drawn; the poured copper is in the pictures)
GND_SIGNAL_B on TOP: 45.29,53.14 45.29,51.54 48.41,51.54 48.41,53.14
GND_SIGNAL_B on TOP: 56.62,50.44 56.62,49.28 59.94,49.28 59.94,50.44
GND_SIGNAL_B on TOP: 48.41,53.11 48.41,56.01 45.92,56.01 45.92,53.11
GND_SIGNAL_B on TOP: 43.92,49.71 43.92,53.87 45.44,53.87 45.44,49.71
GND_SIGNAL_B on 02_GND: 45.97,76.1 47.6,77.72 77.06,77.72 78.74,76.05 78.74,63.65 71.04,55.96 66.9,55.96 57.81,46.86 49.48,46.86 47.96,45.34 46.35,45.34 46.24,45.45 46.24,49.03 45.97,49.3
PGND on TOP: 1.07,0.99 1.07,87.78 87.83,87.78 87.83,0.99 ; 6 cut-outs
PGND on BOTTOM: 1.24,1.22 1.24,87.66 87.73,87.66 87.73,1.22
PGND on 02_GND: 1.27,1.27 1.27,87.63 87.63,87.63 87.63,1.27 ; 1 cut-out
PGND on 03_PWR: 1.07,39.29 1.07,87.43 1.27,87.63 87.63,87.63 87.63,58.85 86.61,57.84 57.33,57.84 50.29,64.87 45.97,64.87 44.07,62.97 44.07,57.96 43.15,57.05 19.84,57.05 2.57,39.78 2.57,39.75 2.11,39.29
PGND on 03_PWR: 1.27,1.27 1.27,26.92 9.78,26.92 9.78,34.54 15.11,39.88 37.59,39.88 38.23,39.24 38.23,34.42 38.63,34.01 40.59,34.01 40.89,33.71 40.89,27.71 43.46,25.15 87.63,25.15 87.63,1.27
VIN on TOP: 46.94,45.39 46.94,44.2 47.19,43.94 48.92,43.94 48.97,43.89 53.92,43.89 54.23,44.2 54.23,46.23 53.98,46.48 48.03,46.48
VIN on TOP: 40.21,45.14 42.14,45.14 42.19,45.09 42.19,44.48 41.83,44.12 40.36,44.12 39.8,43.56 38.18,43.56 36.75,42.14 24.16,42.14 23.62,42.67 23.62,47.24 22.86,48.01 21.59,48.01 21.21,48.39 21.21,51.18 21.59,51.56 28.8,51.56 29.31,51.05 29.31,49.43 30.1,48.64 37.87,48.64 38.23,49 39.52,49 39.7,48.82 39.7,45.64
VIN on TOP, BOTTOM: 1.27,31.85 1.27,19.48 13.23,19.48 13.23,31.85
VIN on 03_PWR: 1.78,37.59 20.07,55.88 45.59,55.88 49.51,51.96 54.67,51.96 54.67,43.05 40.26,43.05 37.72,40.51 27.76,40.51 11.86,24.61 1.78,24.61
SW on TOP: 43.97,45.26 44.96,45.26 44.96,42.14 45.75,41.35 45.75,40.16 45.69,40.11 45.69,40.01 46.66,39.04 46.66,35.36 46.46,35.15 43.41,35.15 39.75,31.5 36.83,31.5 36.2,32.13 36.2,34.52 43.97,42.29
SW on BOTTOM: 46.99,35.81 46.48,35.31 43.56,35.31 39.75,31.5 36.83,31.5 36.2,32.13 36.2,34.57 39.24,37.62 39.24,42.95 39.78,43.48 46.46,43.48 46.99,42.95
SW on 02_GND: 44.09,42.42 44.68,42.42 45.75,41.35 45.75,39.9 46.66,38.99 46.66,35.53 46.41,35.28 43.51,35.28 39.73,31.5 36.83,31.5 36.2,32.13 36.2,34.52
SW on 03_PWR: 40.77,42.29 45.97,42.29 46.99,41.27 46.99,35.18 46.61,34.8 43.05,34.8 39.75,31.5 36.83,31.5 36.2,32.13 36.2,34.54 39.24,37.59 39.24,40.77
VOUT on TOP: 42.42,31.75 42.42,28.07 42.8,27.69 45.59,27.69 45.72,27.56 54.74,27.56 56.01,26.29 68.22,26.29 70.05,28.12 70.05,32.38 68.78,33.66 48.64,33.66 47.12,32.13 42.8,32.13
VOUT on TOP: 81,43.08 87.53,43.08 87.78,43.33 87.78,53.54 87.53,53.8 81,53.8 80.39,53.19 80.39,43.69
VOUT on BOTTOM: 81.03,43.08 86.92,43.08 87.76,43.92 87.76,52.98 86.92,53.82 81.03,53.82 80.39,53.19 80.39,43.71
VOUT on 03_PWR: 55.31,52.58 50.16,52.58 45.09,57.66 45.09,61.7 46.86,63.47 50.22,63.47 56.77,56.92 84.84,56.92 87.12,54.64 87.12,26.29 43.84,26.29 41.91,28.22 41.91,32.51 43.31,33.91 47.37,33.91 47.88,34.42 47.88,41.66 54.99,41.66 55.31,41.97
N16792987 on TOP: 58.8,38.99 72.01,38.99 72.39,38.61 72.39,36.7 71.88,36.2 59.31,36.2 58.8,36.7

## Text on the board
BOTTOM: 04_BOTTOM
Board Geometry/Soldermask Bottom: BOTTOMMASK
Package Geometry/Pastemask Bottom: BOT PASTE
Ref Des/Silkscreen Bottom: NOV 2020 | 305-PD-20-1010 | BOT SILK
TOP: 01_TOP
Board Geometry/Soldermask Top: TOP MASK
Package Geometry/Pastemask Top: TOP PASTE
Ref Des/Silkscreen Top: PGND | VIN | BST | EN | PG | COMP | VCC | NA- | 1V | NA+ | 1.2V | 1.1M | 750K | FB | VOUT | SW | 1.5V | 1.8V | 2.5V | 550K | 3.3V | NCP3237_Eval_Board_RevC | TOP SILK
02_GND: 02_GND
03_PWR: 03_PWR
User.7: FAB
User.11: LAYER  : | DATE : | NAME : | NOV 2020 | NCV3237_Eval_Board_RevC | JOB : | 305-PD-20-1010 | REV.C
User.12: REVISIONS | REV C | NOV 2020 | DATE
User.15: NOTES : | 1) FABRICATE BOARD PER IPC-A-600G | 2) MATERIAL:FR4, 4 LAYER BOARD. | 3) BOARD THICKNESS : 63.00 MILS+/- 10% | 4) NEED 2 oz COPPER ON ALL LAYERS. | 5) FINISH:TIN PLATED | 6) ALL HOLES ARE PLATED THROUGH UNLESS OTHERWISE SPECIFIED. | 7) ALL HOLES ARE IN THE DRILL CHART FINISHED HOLE SIZE | 8) SOLDER MASK BOTH SIDE WITH GREEN LIQUID PHOTO IMAGABLE. | 9) BOARD DIMENSIONS ARE IN INCHES [MM]. | 10) SILKSCREEN BOTH SIDE "WHITE EPOXY" OVER SOLDER MASK | 11) DEBURR ALL SHARP EDGES | 12) BOW AND TWIST: SHOULD NOT EXCEED 0.005" PER INCH. | 13) PLATED PADS ON TOP AND BOTTOM MUST BE SAME HEIGHT AS CONDUCTOR PAD AND TRACE. | 14) NO VENDOR LOGO OR NAME ON THE BOARD. | 15) REMOVE ALL UNUSED PADS IN ALL INNER LAYERS | 16) MINIMUM PLATING IN ALL THE THROUGH HOLE SHALL BE 0.001 INCH Cu. | 17) CLIP THE SILKSCREEN OVER SOLDERMASK. | CHECKED: | CONTROL: | RELEASED: | QUALITY | DRAWN: | DATED: | NOV 2020 | SCALE: | COMPANY: | 408-329-5500 (phone) | 3000 Patrick Henry Dr Santa Clara CA 95054, | TITLE: | CODE: | SIZE: | 408 747 1239 (fax) | DRAWING NO: | SHEET:     OF | REV: | C | NCV3237_Eval_Board_RevC | 305-PD-20-1010
User.20: FIGURE | SIZE | 8.0 | 10.0 | 15.0 | 35.0 | 40.0 | 51.18 | 76.0 | 55.12 | 125.0 | DRILL CHART: TOP to BOTTOM | ALL UNITS ARE IN MILS | TOLERANCE | +3.0/-3.0 | +4.0/-0.0 | +2.0/-0.0 | +2.0/-2.0 | PLATED | NON-PLATED | QTY | 8 | 16 | 809 | 10 | 28 | 4 | 12
User.21: STACKUP: 4 LAYERS | TOTAL THICKNESS: 63.00 mils +/-10% | DIELECTRIC (9.40 mils) | DIELECTRIC (33.86 mils) | 01_TOP (1 oz + PLATING) | 02_GND (2 oz) | 03_PWR (2 oz) | 04_BOTTOM (1 oz + PLATING) | (2oz FINISHED) | FR-4
